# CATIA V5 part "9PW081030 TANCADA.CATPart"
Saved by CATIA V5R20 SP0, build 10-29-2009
Part number: 9PW081030 TANCADA
Revision: ANY
Definition: UNKNOWN
Nomenclature: 9PW081030 TANCADA
Source: Unknown
Bounding box of the stored display mesh (mm): x -175 to 0, y -6.7 to 4.5, z -5.1 to 5.1
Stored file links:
  C:\Users\Utente\Desktop\IO LAVORO\3D X SITO CF\CUMSA\3D files PW\pw081030\pw081030_injection\9PW081030 TANCADA.CATPart
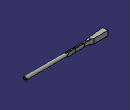
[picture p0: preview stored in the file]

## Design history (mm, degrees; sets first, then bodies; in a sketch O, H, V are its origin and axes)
Body1 "Chaflán4" (main body)
  Solid1: solid without history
